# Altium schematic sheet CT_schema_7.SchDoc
size 278 x 170 mm
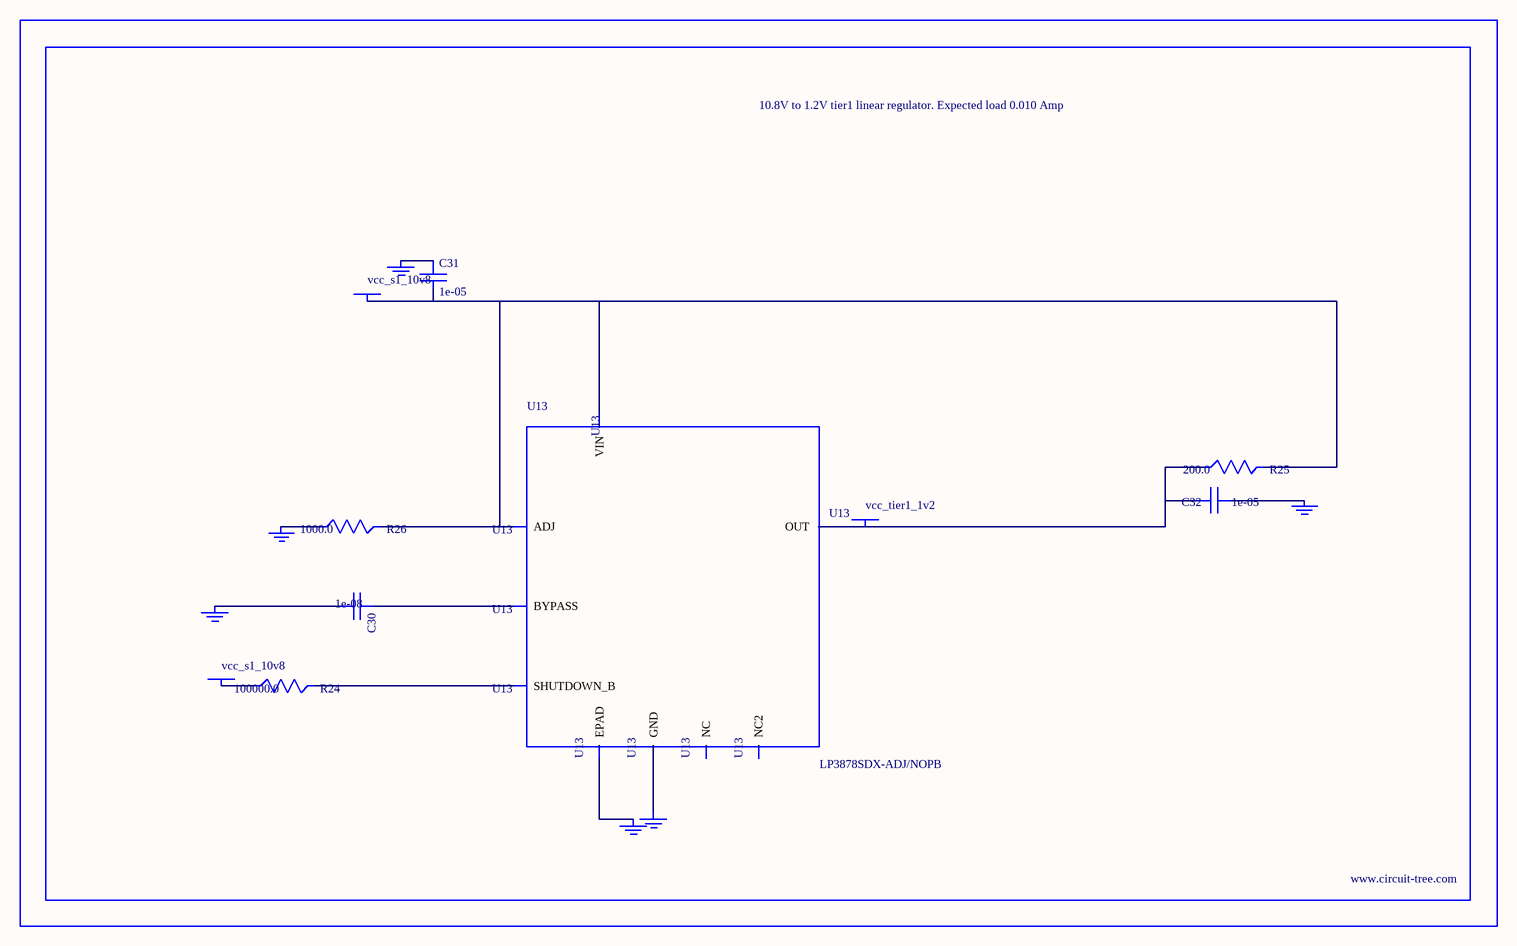
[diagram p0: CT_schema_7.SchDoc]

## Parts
BORDER6  (no value)
C30  1e-08  [C0402]
C31  1e-05  [C1206]
C32  1e-05  [C0805]
GND_INSTANCE_6_0  (no value)
GND_INSTANCE_6_1  (no value)
GND_INSTANCE_6_2  (no value)
GND_INSTANCE_6_3  (no value)
GND_INSTANCE_6_4  (no value)
GND_INSTANCE_6_5  (no value)
POWER_INSTANCE_6_0  vcc_s1_10v8
POWER_INSTANCE_6_1  vcc_s1_10v8
POWER_INSTANCE_6_2  vcc_tier1_1v2
R24  100000.0  [R0603]
R25  200.0  [R0603]
R26  1000.0  [R0603]
U13  LP3878SDX-ADJ/NOPB  [WSON-8]

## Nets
NetC30_1: C30.1 U13.1(BYPASS)
NetC30_2: C30.2 GND_INSTANCE_6_0.0(GND)
NetC31_1: C31.1 GND_INSTANCE_6_1.0(GND)
NetC31_2: C31.2 POWER_INSTANCE_6_0.0(PWR) R25.2 R26.2 U13.4(VIN) U13.6(ADJ)
NetC32_1: C32.1 GND_INSTANCE_6_2.0(GND)
NetC32_2: C32.2 POWER_INSTANCE_6_2.0(PWR) R25.1 U13.5(OUT)
NetGND_INSTANCE_6_3_0: GND_INSTANCE_6_3.0(GND) R26.1
NetGND_INSTANCE_6_4_0: GND_INSTANCE_6_4.0(GND) U13.PAD(EPAD)
NetGND_INSTANCE_6_5_0: GND_INSTANCE_6_5.0(GND) U13.3(GND)
NetPOWER_INSTANCE_6_1_0: POWER_INSTANCE_6_1.0(PWR) R24.1
NetR24_2: R24.2 U13.8(SHUTDOWN_B)

Not connected (* = marked no-connect by the designer): U13 2(NC) 7(NC2)

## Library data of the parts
BORDER6 = BORDER_PAGE6
C30 = C0402C103K3RAC
C31 = C1206C106K3RACTU
C32 = GRM219R60J106ME19D
GND_INSTANCE_6_0-GND_INSTANCE_6_5 = GND
POWER_INSTANCE_6_0-POWER_INSTANCE_6_2 = PWR
R24 = RC0603JR-07100KL
R25 = RC0603JR-07200RL
R26 = RC0603JR-071KL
